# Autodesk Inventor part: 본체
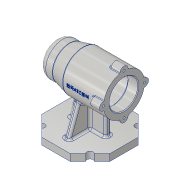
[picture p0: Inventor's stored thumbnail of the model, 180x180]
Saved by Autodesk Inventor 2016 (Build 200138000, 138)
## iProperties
Created: 2021-01
Part Number: 본체
Material: 알루미늄 6061
Document SubType Name: Modeling
Designer: Administrator
Density: 2.7 g/cm^3
Appearance: 알루미늄 - 평지
Mass: 629.963 g
Surface Area: 613.782 cm^2
Volume: 233.32 cm^3
Author: Administrator
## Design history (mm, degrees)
sketch "스케치1"
  geometry: L1 (-50, 0)-(50, 0); L2 (-50, 0)-(-50, 25); L3 (-50, 25)-(-30, 25); L4 (-30, 25)-(-10, 30); L5 (-10, 30)-(50, 30); L6 (50, 30)-(50, 0); 1 further point
  constraints: 12 end point, 2 perpendicular, 1 horizontal, 1 midpoint, 1 parallel, 1 vertical
  dimensions: "d1" = 50 distance of point (0, 0) L1.start; "d2" = 100 distance of L1.end L1.start; "d3" = 20 distance of L2.end L3.end; "d4" = 40 distance from line of L4.end L2; "d5" = 50 diameter of L3 L1; "d6" = 60 diameter of L5 L1
revolve "회전1" sketch "스케치1" stored, may be unused: angle "d7" = 90 deg
node "작업 평면1"
sketch "스케치2" dims "d9" = 50
  geometry: L1 (-20.711, -50)-(-50, -20.711); L2 (-50, -20.711)-(-50, 20.711); L3 (-50, 20.711)-(-20.711, 50); L4 (-20.711, 50)-(20.711, 50); L5 (20.711, 50)-(50, 20.711); L6 (50, 20.711)-(50, -20.711); L7 (50, -20.711)-(20.711, -50); L8 (20.711, -50)-(-20.711, -50); 4 further points
  constraints: 16 end point, 2 coincident, 1 horizontal, 1 midpoint, 1 vertical alignment, 19 other
extrude "돌출1" join sketch "스케치2" distance "d10" = 10; taper "d11" = 0 deg
sketch "스케치3"
  geometry: L1 (0, 4)-(27, 4); L2 (27, 4)-(27, -4); L3 (27, -4)-(0, -4); L4 (0, -4)-(0, 4); L5 (50, 20.711)-(50, -20.711) reference; 1 further point
  constraints: 8 end point, 2 parallel, 1 horizontal, 1 midpoint, 1 perpendicular
  dimensions: "d12" = 23 distance between parallel lines of L5 L2; "d13" = 8 distance between parallel lines of L3 L1; "d14" = 4 distance from line of point (0, 0) L1
extrude "돌출2" join sketch "스케치3" stored distance "d15" = 10; taper "d16" = 0 deg
sketch "스케치4"
  geometry: L1 (-19.2, -24.873)-(-27, -65); L2 (-20.711, -65)-(-50, -65) reference; 1 further point
  constraints: 2 end point, 1 point on line
  dimensions: "d17" = 23 distance of L1.end L2.end; "d18" = 101 deg angle of L2 L1
feature "리브1" sketch "스케치4" dims "d19" = 1, "d20" = 8, "d21" = 0, "d22" = 0, "d23" = 1, "d24" = 1
sketch "스케치5"
  geometry: L1 (-22.707, 19.606)-(-65, 35); L2 (-65, 20.711)-(-65, 50) reference; A1 r 30 centre (0, 0) between (-29.732, -4) and (-29.732, 4) reference; 1 further point
  constraints: 2 end point, 1 point on circle, 1 point on line
  dimensions: "d25" = 15 distance of L1.end L2.end; "d26" = 110 deg angle of L2 L1
feature "리브2" sketch "스케치5" dims "d27" = 1, "d28" = 8, "d29" = 0, "d30" = 0, "d31" = 1, "d32" = 1
sketch "스케치6"
  geometry: C1 r 6 at (0, 30); C2 r 6 at (-30, 0); C3 r 6 at (0, -30); C4 r 6 at (30, 0); 2 further points
  constraints: 4 centre point, 2 vertical alignment, 10 other
  dimensions: "d33" = 6 radius of C1; "d36" = 360 deg dimension on point (0, 0) C1.centre (derived)
extrude "돌출3" join sketch "스케치6" distance "d38" = 16; taper "d39" = 0 deg
sketch "스케치7"
  geometry: A1 r 30 centre (30, 0) between (59.4, 5.97) and (35.97, 29.4) reference; A2 r 6 centre (30, 30) between (35.97, 29.4) and (24.03, 29.4) reference; A3 r 30 centre (30, 0) between (24.03, 29.4) and (0.6, 5.97) reference; A4 r 6 centre (0, 0) between (0.6, 5.97) and (0.6, -5.97) reference; A5 r 30 centre (30, 0) between (0.6, -5.97) and (24.03, -29.4) reference; A6 r 6 centre (30, -30) between (24.03, -29.4) and (35.97, -29.4) reference; A7 r 30 centre (30, 0) between (35.97, -29.4) and (59.4, -5.97) reference; A8 r 6 centre (60, 0) between (59.4, -5.97) and (59.4, 5.97) reference; 1 further point
hole "구멍1" sketch "스케치7" at (30, 30), (0, 0), (30, -30), (60, 0) diameter "d40" = 3.242; stored, may be unused: countersink angle "d44" = 90 deg, drill point angle "d46" = 120 deg; dims "d41" = 8, "d42" = 4, "d43" = 2, "d45" = 10
sketch "스케치8"
  geometry: L1 (-50, 20.711)-(-20.711, 50) reference; L2 (0, 0)-(-35.355, 35.355); C1 r 4.5 at (-35.355, 35.355); C2 r 4.5 at (-35.355, -35.355); C3 r 4.5 at (35.355, -35.355); C4 r 4.5 at (35.355, 35.355)
  constraints: 4 centre point, 2 end point, 1 coincident, 1 midpoint, 1 perpendicular, 9 other
  dimensions: "d48" = 9 diameter of C1; "d51" = 360 deg dimension on L2.start C1.centre (derived)
extrude "돌출4" cut sketch "스케치8" distance "d53" = 16; taper "d54" = 0 deg
hole "구멍2" diameter "d57" = 42; stored, may be unused: countersink angle "d61" = 90 deg, drill point angle "d63" = 0 deg; dims "d55" = 10, "d56" = 10, "d58" = 8, "d59" = 4, "d60" = 2, "d62" = 15
hole "구멍3" diameter "d66" = 42; stored, may be unused: countersink angle "d70" = 90 deg, drill point angle "d72" = 0 deg; dims "d64" = 10, "d65" = 10, "d67" = 8, "d68" = 48, "d69" = 42, "d71" = 54
hole "구멍4" diameter "d75" = 32; stored, may be unused: countersink angle "d79" = 90 deg, drill point angle "d81" = 0 deg; dims "d73" = 10, "d74" = 10, "d76" = 8, "d77" = 35, "d78" = 18, "d80" = 22
hole "구멍5" diameter "d84" = 21; stored, may be unused: countersink angle "d88" = 90 deg, drill point angle "d90" = 0 deg; dims "d82" = 10, "d83" = 10, "d85" = 8, "d86" = 35, "d87" = 18, "d89" = 3
node "작업 평면2"
sketch "스케치9"
  geometry: L1 (30, 5.97)-(30, 29.4) reference; 2 further points
  constraints: 1 horizontal alignment, 1 other
  dimensions: "d91" = 38 distance from line of L1 point (-8, 0)
feature "엠보싱1" sketch "스케치9" dims "d92" = 0.5, "d93" = 0
fillet "모깎기1" dims "d94" = 10
chamfer "모따기1" distance "d95" = 1; stored, may be unused: second distance "d96" = 2, angle "d97" = 45 deg
fillet "모깎기2" dims "d98" = 3
fillet "모깎기3" dims "d99" = 1
fillet "모깎기4" dims "d100" = 3
fillet "모깎기5" dims "d101" = 0.3
fillet "모깎기6" dims "d102" = 3
node "솔리드1"
mirror "대칭1"
node "투영된 루프1"
other parameters: "d8" = -75
